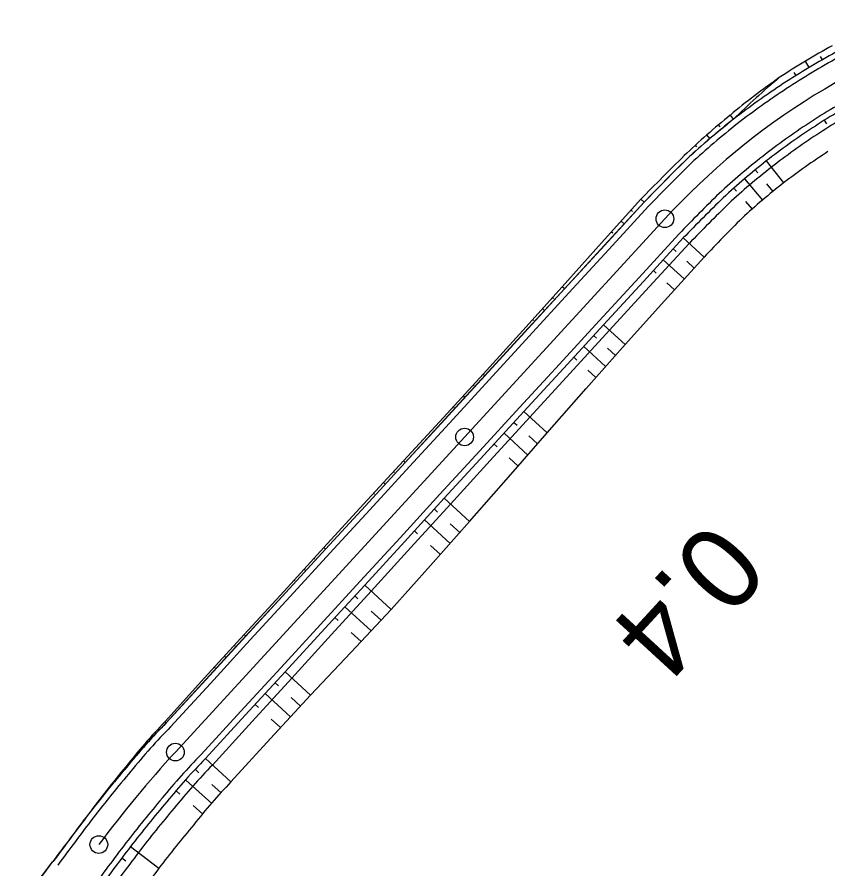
# Model space of a CAD drawing. Extents: x -481645 to -478728, y -1113199 to -1110710.
# Drawn here: x -479677.3 to -479608.4, y -1111510 to -1111437.6 of the extents above; entities that cross this region are included whole.
import ezdxf

# ---------------------------------------------------------------- set-up
doc = ezdxf.new("R2010")
doc.units = 0
for name, color, linetype in [('CP14_HATCH_SLOPE_L', 7, 'Continuous'), ('CP1_HECTOMETRY', 7, 'Continuous'), ('O6_HATCH_SLOPE_L', 7, 'Continuous'), ('O6_HATCH_SLOPE_R', 7, 'Continuous'), ('O6_HECTOMETRY', 7, 'Continuous'), ('O6_HRANA_TELESO', 7, 'Continuous'), ('O6_OSA', 7, 'Continuous'), ('O6_VOZOVKA', 7, 'Continuous'), ('O6_ZPEVKRAJ', 7, 'Continuous')]:
    doc.layers.add(name, color=color, linetype=linetype)

msp = doc.modelspace()

# ---------------------------------------------------------------- linework, layer by layer
at = {"layer": 'CP14_HATCH_SLOPE_L'}
for p, q in [((-479608.75, -1111446.389), (-479608.567, -1111446.68)), ((-479613.671, -1111449.845), (-479612.21, -1111451.711)), ((-479614.61, -1111450.596), (-479614.394, -1111450.862)), ((-479615.534, -1111451.367), (-479613.999, -1111453.168)), ((-479613.645, -1111451.778), (-479613.112, -1111452.43)), ((-479616.441, -1111452.157), (-479616.213, -1111452.413)), ((-479615.428, -1111453.296), (-479614.87, -1111453.924)), ((-479620.725, -1111456.385), (-479618.959, -1111458.005)), ((-479621.57, -1111457.306), (-479621.318, -1111457.537)), ((-479622.415, -1111458.228), (-479620.632, -1111459.862)), ((-479620.431, -1111458.351), (-479619.796, -1111458.934)), ((-479623.26, -1111459.149), (-479623.008, -1111459.379)), ((-479622.113, -1111460.2), (-479621.469, -1111460.791)), ((-479627.484, -1111463.755), (-479625.648, -1111465.439)), ((-479628.329, -1111464.676), (-479628.078, -1111464.906)), ((-479629.174, -1111465.597), (-479627.31, -1111467.307)), ((-479627.153, -1111465.754), (-479626.479, -1111466.373)), ((-479630.019, -1111466.518), (-479629.767, -1111466.749)), ((-479628.828, -1111467.61), (-479628.141, -1111468.241)), ((-479634.244, -1111471.124), (-479632.278, -1111472.928)), ((-479635.089, -1111472.045), (-479634.832, -1111472.28)), ((-479635.934, -1111472.966), (-479633.916, -1111474.817)), ((-479633.836, -1111473.194), (-479633.097, -1111473.872)), ((-479636.779, -1111473.887), (-479636.519, -1111474.125)), ((-479635.498, -1111475.062), (-479634.736, -1111475.762)), ((-479641.004, -1111478.493), (-479638.855, -1111480.464)), ((-479641.849, -1111479.414), (-479641.582, -1111479.66)), ((-479642.694, -1111480.335), (-479640.509, -1111482.339)), ((-479640.498, -1111480.654), (-479639.682, -1111481.402)), ((-479643.539, -1111481.257), (-479643.268, -1111481.504)), ((-479642.167, -1111482.514), (-479641.336, -1111483.277)), ((-479647.764, -1111485.862), (-479645.509, -1111487.931)), ((-479648.609, -1111486.783), (-479648.33, -1111487.038)), ((-479649.454, -1111487.705), (-479647.219, -1111489.755)), ((-479647.208, -1111488.068), (-479646.364, -1111488.843)), ((-479650.298, -1111488.626), (-479650.017, -1111488.884)), ((-479648.905, -1111489.904), (-479648.074, -1111490.667)), ((-479654.523, -1111493.232), (-479652.348, -1111495.227)), ((-479655.368, -1111494.153), (-479655.079, -1111494.418)), ((-479656.213, -1111495.074), (-479654.054, -1111497.055)), ((-479653.996, -1111495.412), (-479653.201, -1111496.141)), ((-479657.058, -1111495.995), (-479656.766, -1111496.263)), ((-479655.69, -1111497.25), (-479654.906, -1111497.969)), ((-479661.283, -1111500.601), (-479659.117, -1111502.588)), ((-479662.128, -1111501.522), (-479661.828, -1111501.798)), ((-479662.95, -1111502.428), (-479660.736, -1111504.411)), ((-479663.759, -1111503.343), (-479663.45, -1111503.614)), ((-479660.739, -1111502.796), (-479659.95, -1111503.52)), ((-479662.324, -1111504.597), (-479661.508, -1111505.31)), ((-479667.632, -1111508.067), (-479665.235, -1111509.911)), ((-479668.371, -1111509.04), (-479668.033, -1111509.294))]:
    msp.add_line(p, q, dxfattribs=at)
at = {"layer": 'CP1_HECTOMETRY'}
msp.add_line((-479663.832, -1111500.051), (-479622.283, -1111454.755), dxfattribs=at)
for centre, radius, start, end in [((-479578.067, -1111495.314), 60, 105.93368, 137.47016), ((-479590.139, -1111567.648), 100, 137.47018, 143.31086)]:
    msp.add_arc(centre, radius, start, end, dxfattribs=at)
at = {"layer": 'O6_HATCH_SLOPE_L'}
msp.add_circle((-479639.282, -1111473.288), 0.75, dxfattribs=at)
msp.add_circle((-479639.282, -1111473.288), 0.75, dxfattribs=at)
at = {"layer": 'O6_HATCH_SLOPE_R'}
for p, q in [((-479609.227, -1111440.699), (-479609.227, -1111440.699)), ((-479608.916, -1111441.245), (-479609.072, -1111440.972)), ((-479610.035, -1111441.899), (-479610.355, -1111441.365)), ((-479611.469, -1111442.054), (-479611.469, -1111442.054)), ((-479611.141, -1111442.577), (-479611.305, -1111442.316)), ((-479616.445, -1111446.302), (-479616.726, -1111445.943)), ((-479617.598, -1111446.94), (-479617.733, -1111446.775)), ((-479618.454, -1111447.943), (-479618.722, -1111447.628)), ((-479617.458, -1111447.112), (-479617.461, -1111447.108)), ((-479619.566, -1111448.644), (-479619.693, -1111448.501)), ((-479619.432, -1111448.794), (-479619.435, -1111448.79)), ((-479624.041, -1111453.343), (-479624.312, -1111453.094)), ((-479625.022, -1111454.14), (-479625.15, -1111454.022)), ((-479624.886, -1111454.265), (-479624.89, -1111454.262)), ((-479625.731, -1111455.186), (-479625.988, -1111454.95)), ((-479626.704, -1111455.989), (-479626.825, -1111455.878)), ((-479626.576, -1111456.107), (-479626.58, -1111456.104)), ((-479630.801, -1111460.713), (-479631.009, -1111460.522)), ((-479631.748, -1111461.54), (-479631.842, -1111461.454)), ((-479631.645, -1111461.634), (-479631.649, -1111461.63)), ((-479632.49, -1111462.555), (-479632.675, -1111462.386)), ((-479633.425, -1111463.394), (-479633.507, -1111463.318)), ((-479633.335, -1111463.476), (-479633.339, -1111463.472)), ((-479637.56, -1111468.082), (-479637.7, -1111467.954)), ((-479638.478, -1111468.936), (-479638.544, -1111468.876)), ((-479638.405, -1111469.003), (-479638.409, -1111469)), ((-479639.25, -1111469.924), (-479639.388, -1111469.798)), ((-479640.168, -1111470.779), (-479640.233, -1111470.719)), ((-479640.095, -1111470.845), (-479640.099, -1111470.842)), ((-479644.32, -1111475.451), (-479644.474, -1111475.31)), ((-479645.246, -1111476.298), (-479645.321, -1111476.229)), ((-479645.165, -1111476.372), (-479645.168, -1111476.369)), ((-479646.01, -1111477.294), (-479646.169, -1111477.148)), ((-479646.939, -1111478.138), (-479647.016, -1111478.067)), ((-479646.855, -1111478.215), (-479646.858, -1111478.212)), ((-479651.08, -1111482.82), (-479651.229, -1111482.684)), ((-479652.002, -1111483.67), (-479652.072, -1111483.606)), ((-479651.925, -1111483.742), (-479651.928, -1111483.738)), ((-479652.77, -1111484.663), (-479652.916, -1111484.528)), ((-479653.691, -1111485.514), (-479653.76, -1111485.45)), ((-479653.615, -1111485.584), (-479653.618, -1111485.58)), ((-479657.839, -1111490.19), (-479657.98, -1111490.061)), ((-479658.758, -1111491.044), (-479658.824, -1111490.983)), ((-479658.684, -1111491.111), (-479658.688, -1111491.108)), ((-479659.529, -1111492.032), (-479659.668, -1111491.905)), ((-479660.446, -1111492.886), (-479660.511, -1111492.827)), ((-479660.374, -1111492.953), (-479660.378, -1111492.95)), ((-479664.599, -1111497.559), (-479664.708, -1111497.46)), ((-479665.496, -1111498.432), (-479665.541, -1111498.392)), ((-479665.444, -1111498.48), (-479665.448, -1111498.476)), ((-479666.302, -1111499.426), (-479666.387, -1111499.349)), ((-479667.19, -1111500.347), (-479667.223, -1111500.318)), ((-479667.149, -1111500.383), (-479667.152, -1111500.38)), ((-479671.982, -1111506.335), (-479671.984, -1111506.334)), ((-479671.972, -1111506.342), (-479671.976, -1111506.339))]:
    msp.add_line(p, q, dxfattribs=at)
at = {"layer": 'O6_HECTOMETRY'}
for centre in [(-479622.283, -1111454.755), (-479622.283, -1111454.755), (-479663.832, -1111500.051), (-479663.832, -1111500.051), (-479670.328, -1111507.901)]:
    msp.add_circle(centre, 0.75, dxfattribs=at)
at = {"layer": 'O6_HRANA_TELESO'}
for p, q in [((-479627.428, -1111457.021), (-479624.048, -1111453.337)), ((-479630.808, -1111460.706), (-479627.428, -1111457.021)), ((-479623.603, -1111460.53), (-479620.221, -1111456.847)), ((-479634.188, -1111464.391), (-479630.808, -1111460.706)), ((-479626.983, -1111464.215), (-479623.603, -1111460.53)), ((-479637.568, -1111468.075), (-479634.188, -1111464.391)), ((-479630.36, -1111467.902), (-479626.983, -1111464.215)), ((-479633.733, -1111471.593), (-479630.36, -1111467.902)), ((-479640.947, -1111471.76), (-479637.568, -1111468.075)), ((-479637.103, -1111475.287), (-479633.733, -1111471.593)), ((-479644.327, -1111475.444), (-479640.947, -1111471.76)), ((-479640.472, -1111478.981), (-479637.103, -1111475.287)), ((-479647.707, -1111479.129), (-479644.327, -1111475.444)), ((-479651.087, -1111482.814), (-479647.707, -1111479.129)), ((-479643.841, -1111482.676), (-479640.472, -1111478.981)), ((-479654.467, -1111486.498), (-479651.087, -1111482.814)), ((-479647.21, -1111486.37), (-479643.841, -1111482.676)), ((-479657.847, -1111490.183), (-479654.467, -1111486.498)), ((-479650.579, -1111490.065), (-479647.21, -1111486.37)), ((-479661.227, -1111493.868), (-479657.847, -1111490.183)), ((-479653.948, -1111493.76), (-479650.579, -1111490.065)), ((-479664.607, -1111497.552), (-479661.227, -1111493.868)), ((-479657.317, -1111497.454), (-479653.948, -1111493.76)), ((-479660.686, -1111501.149), (-479657.317, -1111497.454)), ((-479677.212, -1111513.357), (-479674.225, -1111509.348))]:
    msp.add_line(p, q, dxfattribs=at)
for centre, radius, start, end in [((-479572.483, -1111490.798), 62.561, 129.84664, 134.65292), ((-479578.084, -1111495.324), 57.061, 118.49276, 123.26741), ((-479578.067, -1111495.314), 62.26, 128.06227, 132.83692), ((-479578.084, -1111495.326), 57.063, 123.26722, 128.04187), ((-479489.657, -1111583.051), 186.78, 134.42502, 136.01445), ((-479578.082, -1111495.327), 57.065, 128.04206, 132.8167), ((-479497.068, -1111575.765), 171.197, 134.40859, 136.00218), ((-479628.199, -1111533.452), 51.13, 135.40269, 141.10083), ((-479590.139, -1111567.648), 102.26, 139.58019, 142.44498), ((-479626.106, -1111535.102), 48.462, 135.52424, 141.30399), ((-479589.954, -1111567.418), 96.917, 139.75479, 142.61959), ((-479435.19, -1111684.089), 290.729, 142.86561, 143.84179)]:
    msp.add_arc(centre, radius, start, end, dxfattribs=at)
at = {"layer": 'O6_OSA'}
for p, q in [((-479627.663, -1111456.806), (-479624.312, -1111453.094)), ((-479631.009, -1111460.522), (-479627.663, -1111456.806)), ((-479622.306, -1111461.72), (-479618.959, -1111458.005)), ((-479634.34, -1111464.251), (-479631.009, -1111460.522)), ((-479625.648, -1111465.439), (-479622.306, -1111461.72)), ((-479637.7, -1111467.954), (-479634.34, -1111464.251)), ((-479628.971, -1111469.175), (-479625.648, -1111465.439)), ((-479641.077, -1111471.641), (-479637.7, -1111467.954)), ((-479632.278, -1111472.928), (-479628.971, -1111469.175)), ((-479644.474, -1111475.31), (-479641.077, -1111471.641)), ((-479635.555, -1111476.706), (-479632.278, -1111472.928)), ((-479647.864, -1111478.985), (-479644.474, -1111475.31)), ((-479638.855, -1111480.464), (-479635.555, -1111476.706)), ((-479651.229, -1111482.684), (-479647.864, -1111478.985)), ((-479642.163, -1111484.215), (-479638.855, -1111480.464)), ((-479654.604, -1111486.372), (-479651.229, -1111482.684)), ((-479645.509, -1111487.931), (-479642.163, -1111484.215)), ((-479657.98, -1111490.061), (-479654.604, -1111486.372)), ((-479648.929, -1111491.579), (-479645.509, -1111487.931)), ((-479661.355, -1111493.75), (-479657.98, -1111490.061)), ((-479652.348, -1111495.227), (-479648.929, -1111491.579)), ((-479664.708, -1111497.46), (-479661.355, -1111493.75)), ((-479655.759, -1111498.883), (-479652.348, -1111495.227)), ((-479659.117, -1111502.588), (-479655.759, -1111498.883)), ((-479677.27, -1111513.314), (-479674.229, -1111509.345))]:
    msp.add_line(p, q, dxfattribs=at)
for centre, radius, start, end in [((-479577.825, -1111495.168), 62.873, 118.76987, 123.54456), ((-479576.565, -1111494.201), 62.783, 124.99058, 129.76734), ((-479577.312, -1111494.659), 62.664, 128.97482, 133.75007), ((-479578.447, -1111495.584), 55.36, 122.80527, 127.58009), ((-479489.043, -1111583.463), 187.867, 134.46783, 136.05695), ((-479578.136, -1111495.372), 55.383, 127.96926, 132.74392), ((-479498.561, -1111572.521), 166.162, 134.83983, 136.43449), ((-479627.821, -1111532.919), 51.166, 136.13073, 141.82927), ((-479589.288, -1111566.582), 102.298, 140.34375, 143.20879), ((-479624.978, -1111535.432), 47.372, 136.10744, 141.9244), ((-479427.164, -1111691.226), 306.793, 142.70049, 143.64067), ((-479589.899, -1111567.351), 94.735, 139.81113, 142.67594), ((-479436.283, -1111678.249), 284.177, 143.67456, 144.6667)]:
    msp.add_arc(centre, radius, start, end, dxfattribs=at)
at = {"layer": 'O6_VOZOVKA'}
for p, q in [((-479627.052, -1111457.366), (-479623.672, -1111453.681)), ((-479624.473, -1111459.732), (-479621.093, -1111456.047)), ((-479630.432, -1111461.051), (-479627.052, -1111457.366)), ((-479627.853, -1111463.417), (-479624.473, -1111459.732)), ((-479633.812, -1111464.735), (-479630.432, -1111461.051)), ((-479631.233, -1111467.101), (-479627.853, -1111463.417)), ((-479637.192, -1111468.42), (-479633.812, -1111464.735)), ((-479634.613, -1111470.786), (-479631.233, -1111467.101)), ((-479640.572, -1111472.105), (-479637.192, -1111468.42)), ((-479637.992, -1111474.47), (-479634.613, -1111470.786)), ((-479643.952, -1111475.789), (-479640.572, -1111472.105)), ((-479641.372, -1111478.155), (-479637.992, -1111474.47)), ((-479647.331, -1111479.474), (-479643.952, -1111475.789)), ((-479644.752, -1111481.84), (-479641.372, -1111478.155)), ((-479650.711, -1111483.158), (-479647.331, -1111479.474)), ((-479648.132, -1111485.524), (-479644.752, -1111481.84)), ((-479654.091, -1111486.843), (-479650.711, -1111483.158)), ((-479651.512, -1111489.209), (-479648.132, -1111485.524)), ((-479657.471, -1111490.528), (-479654.091, -1111486.843)), ((-479654.892, -1111492.894), (-479651.512, -1111489.209)), ((-479660.851, -1111494.212), (-479657.471, -1111490.528)), ((-479658.272, -1111496.578), (-479654.892, -1111492.894)), ((-479664.231, -1111497.897), (-479660.851, -1111494.212)), ((-479661.652, -1111500.263), (-479658.272, -1111496.578))]:
    msp.add_line(p, q, dxfattribs=at)
for centre, radius, start, end in [((-479578.067, -1111495.314), 61.75, 118.51298, 123.28763), ((-479578.067, -1111495.314), 61.75, 123.28763, 128.06227), ((-479578.067, -1111495.314), 58.25, 118.51297, 123.28762), ((-479578.067, -1111495.314), 61.75, 128.06227, 132.83692), ((-479578.067, -1111495.314), 58.25, 123.28762, 128.06227), ((-479578.067, -1111495.314), 58.25, 128.06227, 132.83692), ((-479490.381, -1111582.332), 185.25, 134.42536, 136.01517), ((-479495.345, -1111577.394), 174.75, 134.42787, 136.02042), ((-479628.008, -1111533.62), 50.875, 135.39798, 141.10352), ((-479626.695, -1111534.778), 49.125, 135.36435, 141.12281), ((-479590.139, -1111567.648), 101.75, 139.58019, 142.44498), ((-479590.139, -1111567.648), 98.25, 139.58019, 142.44498), ((-479427.963, -1111690.579), 305.25, 142.70667, 143.65014), ((-479433.568, -1111686.385), 294.75, 142.6982, 143.665)]:
    msp.add_arc(centre, radius, start, end, dxfattribs=at)
at = {"layer": 'O6_ZPEVKRAJ'}
for p, q in [((-479627.421, -1111457.028), (-479624.041, -1111453.343)), ((-479624.104, -1111460.07), (-479620.725, -1111456.385)), ((-479630.801, -1111460.713), (-479627.421, -1111457.028)), ((-479627.484, -1111463.755), (-479624.104, -1111460.07)), ((-479634.18, -1111464.397), (-479630.801, -1111460.713)), ((-479637.56, -1111468.082), (-479634.18, -1111464.397)), ((-479630.864, -1111467.439), (-479627.484, -1111463.755)), ((-479634.244, -1111471.124), (-479630.864, -1111467.439)), ((-479640.94, -1111471.767), (-479637.56, -1111468.082)), ((-479637.624, -1111474.808), (-479634.244, -1111471.124)), ((-479644.32, -1111475.451), (-479640.94, -1111471.767)), ((-479641.004, -1111478.493), (-479637.624, -1111474.808)), ((-479647.7, -1111479.136), (-479644.32, -1111475.451)), ((-479644.384, -1111482.178), (-479641.004, -1111478.493)), ((-479651.08, -1111482.82), (-479647.7, -1111479.136)), ((-479647.764, -1111485.862), (-479644.384, -1111482.178)), ((-479654.46, -1111486.505), (-479651.08, -1111482.82)), ((-479651.143, -1111489.547), (-479647.764, -1111485.862)), ((-479657.839, -1111490.19), (-479654.46, -1111486.505)), ((-479654.523, -1111493.232), (-479651.143, -1111489.547)), ((-479661.219, -1111493.874), (-479657.839, -1111490.19)), ((-479657.903, -1111496.916), (-479654.523, -1111493.232)), ((-479664.599, -1111497.559), (-479661.219, -1111493.874)), ((-479661.283, -1111500.601), (-479657.903, -1111496.916))]:
    msp.add_line(p, q, dxfattribs=at)
for centre, radius, start, end in [((-479578.067, -1111495.314), 62.25, 118.51298, 123.28763), ((-479578.067, -1111495.314), 62.25, 123.28763, 128.06227), ((-479578.067, -1111495.314), 57.75, 118.51297, 123.28762), ((-479578.067, -1111495.314), 62.25, 128.06227, 132.83692), ((-479578.067, -1111495.314), 57.75, 123.28762, 128.06227), ((-479489.671, -1111583.037), 186.75, 134.42502, 136.01446), ((-479578.067, -1111495.314), 57.75, 128.06227, 132.83691), ((-479496.054, -1111576.689), 173.25, 134.42825, 136.02122), ((-479628.195, -1111533.455), 51.125, 135.4026, 141.10088), ((-479626.507, -1111534.943), 48.875, 135.35936, 141.12569), ((-479590.139, -1111567.648), 102.25, 139.58019, 142.44498), ((-479590.139, -1111567.648), 97.75, 139.58019, 142.44498), ((-479427.163, -1111691.178), 306.75, 142.70782, 143.64809), ((-479434.369, -1111685.786), 293.25, 142.69693, 143.6672)]:
    msp.add_arc(centre, radius, start, end, dxfattribs=at)

# ---------------------------------------------------------------- texts
at = {"layer": 'O6_HATCH_SLOPE_L'}
msp.add_text('0.4', height=7, rotation=227.42454, dxfattribs=at).set_placement((-479618.426, -1111480.149))

doc.saveas('drawing.dxf')
